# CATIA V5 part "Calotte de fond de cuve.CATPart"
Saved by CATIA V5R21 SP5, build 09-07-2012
Part number: Calotte de fond de cuve
Bounding box of the stored display mesh (mm): x -2021.472 to 2021.472, y -2019.385 to 2019.385, z -2411 to -1233.063
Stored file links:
  \\etu.ad.univ-lorraine.fr\bordron1\Documents\Parts EPR\Calotte de fond de cuve.CATPart
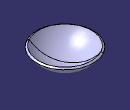
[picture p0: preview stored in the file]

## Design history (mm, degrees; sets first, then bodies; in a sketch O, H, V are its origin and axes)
AxisSystem1: origin (0, 0, 0), X (1, 0, 0), Y (0, 1, 0), Z (0, 0, 1)
Body1 (main body)
  Sketch1 on YZ plane of AxisSystem1, origin (0, 0, 0), H (0, 1, 0), V (0, 0, 1)
    arc A1 centre (0, 0) radius 2264 from (0, -2264) to (1898.7502, -1233.0628) ccw
    point P1 (0, 0)
    point P2 (0, -2264)
    arc A2 centre (0, 0) radius 2411 from (0, -2411) to (2022.0347, -1313.1247) ccw
    point P4 (0, -2411)
    line L1 (0, -2264) -> (0, -2411)
    line L2 (1898.7502, -1233.0628) -> (2022.0347, -1313.1247)
    axis line L3 (0, 0) -> (1898.7502, -1233.0628)
    reference projected line E1 through (0, 0) direction (0, 1) from edge [ZX plane of AxisSystem1 | YZ plane of AxisSystem1]
    radius A1 = 2264
    radius A2 = 2411
    angle L3 E1 = 57
    coincidence: P1 V, P2 V, P4 V, P1 O
    vertical: L1 V
    parallelism: L2 L3
  Shaft1: profile Sketch1, axis edge [ZX plane of AxisSystem1 | YZ plane of AxisSystem1], angle 360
